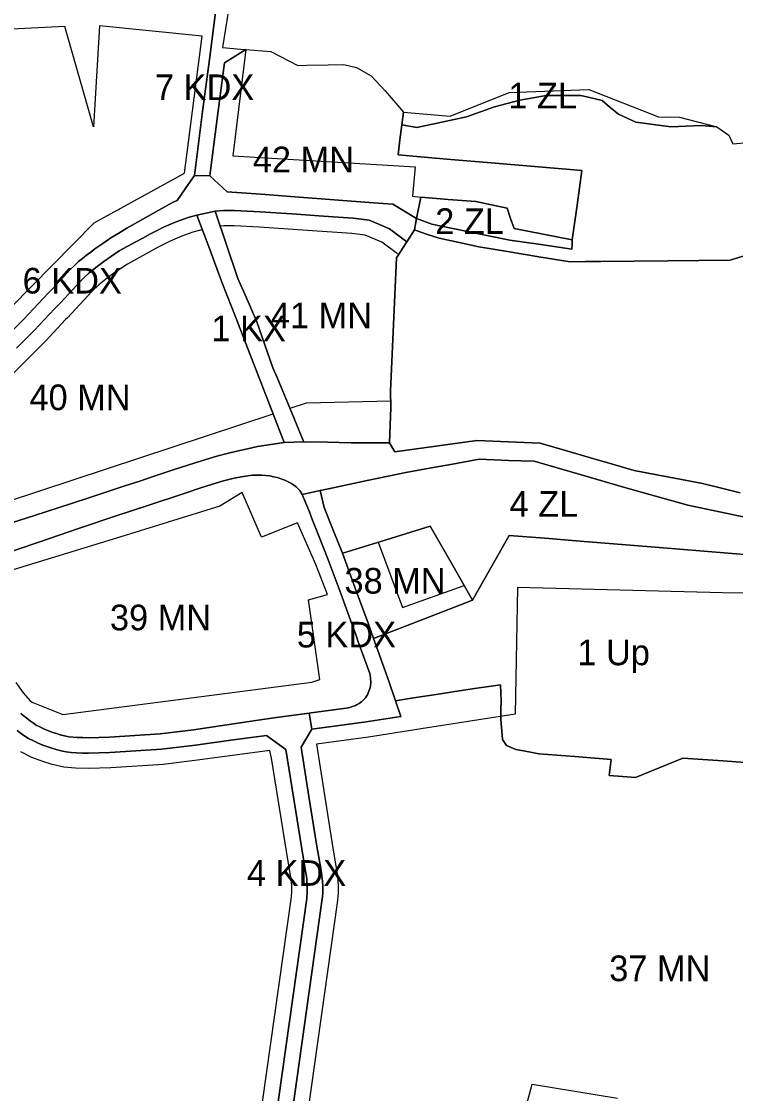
# Model space of a CAD drawing. Extents: x -294445 to -292055, y 21869 to 23693.
# Drawn here: x -293408.1 to -293130, y 23039.5 to 23457 of the extents above; entities that cross this region are included whole.
import ezdxf

# ---------------------------------------------------------------- set-up
doc = ezdxf.new("R2010")
doc.units = 0
for name, color, linetype in [('linie_rozgraniczajace', 7, 'Continuous'), ('linie_zabudowy_nieprzekraczalne', 7, 'Continuous'), ('oznaczenia_przeznaczen', 7, 'Continuous')]:
    doc.layers.add(name, color=color, linetype=linetype)

msp = doc.modelspace()

# ---------------------------------------------------------------- linework, layer by layer
at = {"layer": 'linie_rozgraniczajace'}
for points in [[(-293340.7, 23396.961), (-293339.12, 23409.431), (-293337.54, 23421.9), (-293334.86, 23442.245), (-293332.18, 23462.59), (-293331.728, 23467.542), (-293326.469, 23467.258), (-293329.78, 23446.84), (-293322.6, 23446.24), (-293320.72, 23446.05), (-293328.994, 23440.905), (-293330.292, 23431.018), (-293331.589, 23421.131), (-293333.14, 23409.034), (-293334.691, 23396.937)], [(-293334.691, 23396.937), (-293333.14, 23409.034), (-293331.589, 23421.131), (-293330.292, 23431.018), (-293328.994, 23440.905), (-293320.72, 23446.05), (-293310.92, 23445.34), (-293300.46, 23439.87), (-293296.96, 23439.94), (-293288.57, 23440.11), (-293282.51, 23440.2), (-293277.56, 23439.12), (-293271.9, 23435.79), (-293266.47, 23430.02), (-293259.28, 23421.65), (-293259.99, 23416.77), (-293260.645, 23410.89), (-293261.3, 23405.01), (-293242.445, 23403.395), (-293223.59, 23401.78), (-293206.705, 23400.37), (-293189.82, 23398.96), (-293191.685, 23385.45), (-293193.55, 23371.94), (-293204.855, 23374.15), (-293216.16, 23376.36), (-293217.55, 23380.325), (-293218.94, 23384.29), (-293225.05, 23385.57), (-293231.16, 23386.85), (-293241.858, 23387.69), (-293252.556, 23388.529), (-293254.151, 23380.288), (-293263.46, 23385.81), (-293271.009, 23386.393), (-293286.324, 23387.577), (-293301.64, 23388.76), (-293314.816, 23389.7), (-293327.993, 23390.64)], [(-293259.99, 23416.77), (-293259.28, 23421.65), (-293241.05, 23420.09), (-293218.19, 23429.39), (-293187.11, 23430.52), (-293159.95, 23419.92), (-293151.75, 23419.73), (-293137.26, 23416.03), (-293143.3, 23416.52), (-293149.205, 23416.27), (-293155.11, 23416.02), (-293161.975, 23416.895), (-293168.84, 23417.77), (-293172.165, 23419.31), (-293175.49, 23420.85), (-293178.73, 23423.535), (-293181.97, 23426.22), (-293184.668, 23426.878), (-293187.366, 23427.535), (-293190.18, 23428.24), (-293196.92, 23428.19), (-293203.66, 23428.14), (-293208.815, 23427.235), (-293213.97, 23426.33), (-293218.93, 23425.045), (-293223.89, 23423.76), (-293229.29, 23421.825), (-293234.69, 23419.89), (-293244.375, 23417.795), (-293254.06, 23415.7)], [(-293254.151, 23380.288), (-293252.556, 23388.529), (-293241.858, 23387.69), (-293231.16, 23386.85), (-293225.05, 23385.57), (-293218.94, 23384.29), (-293217.55, 23380.325), (-293216.16, 23376.36), (-293204.855, 23374.15), (-293193.55, 23371.94), (-293193.621, 23370.113), (-293193.69, 23368.36), (-293205.785, 23370.085), (-293217.88, 23371.81), (-293225.483, 23373.38), (-293233.085, 23374.95), (-293240.688, 23376.52), (-293248.29, 23378.09)], [(-293339.717, 23381.629), (-293332.604, 23383.164), (-293328.212, 23370.007), (-293323.82, 23356.85), (-293320.605, 23349.58), (-293316.38, 23340.02), (-293313.245, 23331.09), (-293310.11, 23322.16), (-293308.49, 23318.31), (-293303.405, 23306.09), (-293301.862, 23302.382), (-293298.32, 23293.87), (-293298.09, 23293.301), (-293305.786, 23293.023), (-293312.103, 23309.457), (-293318.42, 23325.89), (-293324.195, 23340.68), (-293329.97, 23355.47), (-293334.843, 23368.55)], [(-293332.604, 23383.164), (-293329.438, 23383.425), (-293327.262, 23383.429), (-293325.086, 23383.434), (-293320.108, 23383.167), (-293315.13, 23382.9), (-293302.8, 23382.05), (-293290.47, 23381.2), (-293284.68, 23380.786), (-293278.889, 23380.371), (-293272.65, 23379.682), (-293268.669, 23377.981), (-293264.687, 23376.279), (-293258.007, 23371.241), (-293262.06, 23364.96), (-293263.185, 23338.966), (-293264.311, 23312.971), (-293264.16, 23306.67), (-293264.425, 23299.77), (-293264.69, 23292.87), (-293272.195, 23292.9), (-293279.7, 23292.93), (-293288.895, 23293.115), (-293298.09, 23293.301), (-293298.32, 23293.87), (-293301.862, 23302.382), (-293303.405, 23306.09), (-293308.49, 23318.31), (-293310.11, 23322.16), (-293313.245, 23331.09), (-293316.38, 23340.02), (-293320.605, 23349.58), (-293323.82, 23356.85), (-293328.212, 23370.007)], [(-293298.776, 23272.823), (-293291.696, 23274.348), (-293290.18, 23267.78), (-293286.63, 23258.85), (-293283.08, 23249.92), (-293278.082, 23236.271), (-293273.085, 23222.623), (-293270.941, 23216.639), (-293268.124, 23208.772), (-293264.885, 23199.73), (-293262.398, 23192.398), (-293260.346, 23186.35), (-293267.068, 23185.28), (-293273.79, 23184.21), (-293284.388, 23182.776), (-293294.986, 23181.343), (-293295.962, 23187.663), (-293295.239, 23187.758), (-293280.658, 23189.726), (-293279.894, 23189.961), (-293279.184, 23190.18), (-293278.728, 23190.321), (-293277.963, 23190.625), (-293277.546, 23190.822), (-293277.083, 23191.069), (-293276.527, 23191.41), (-293276.069, 23191.73), (-293275.525, 23192.164), (-293275.095, 23192.554), (-293274.616, 23193.048), (-293274.14, 23193.614), (-293273.728, 23194.183), (-293273.335, 23194.818), (-293272.981, 23195.498), (-293272.714, 23196.119), (-293272.471, 23196.816), (-293272.275, 23197.55), (-293272.162, 23198.123), (-293272.095, 23198.601), (-293272.046, 23199.145), (-293272.029, 23199.972), (-293272.064, 23200.72), (-293272.099, 23201.469), (-293272.447, 23203.049), (-293274.729, 23209.42), (-293277.01, 23215.79), (-293277.87, 23218.19), (-293278.73, 23220.59), (-293283.708, 23234.185), (-293288.686, 23247.78), (-293292.348, 23256.991), (-293294.934, 23263.496), (-293295.924, 23265.987), (-293297.35, 23269.405)], [(-293283.08, 23249.92), (-293281.151, 23250.514), (-293265.985, 23255.185), (-293248.89, 23260.45), (-293240.64, 23246.02), (-293232.39, 23231.59), (-293234.72, 23230.69), (-293252.765, 23223.69), (-293270.941, 23216.639), (-293273.085, 23222.623), (-293278.082, 23236.271)]]:
    msp.add_lwpolyline(points, close=True, dxfattribs=at)
for points in [[(-293332.18, 23462.59), (-293334.86, 23442.245), (-293337.54, 23421.9), (-293339.12, 23409.431), (-293340.7, 23396.961), (-293344.07, 23392.156), (-293347.44, 23387.35), (-293348.925, 23386.63), (-293350.41, 23385.91), (-293358.707, 23381.184), (-293367.003, 23376.459), (-293370.111, 23374.573), (-293373.219, 23372.687), (-293376.321, 23370.558), (-293379.423, 23368.43), (-293381.066, 23367.195), (-293382.709, 23365.96), (-293384.271, 23364.717), (-293385.833, 23363.475), (-293387.501, 23361.867), (-293389.17, 23360.26), (-293392.4, 23356.77), (-293395.63, 23353.28), (-293397.61, 23351.21), (-293403.416, 23345.064), (-293407.242, 23340.987), (-293414.293, 23333.914)], [(-293261.3, 23405.01), (-293260.645, 23410.89), (-293259.99, 23416.77), (-293254.06, 23415.7), (-293244.375, 23417.795), (-293234.69, 23419.89), (-293229.29, 23421.825), (-293223.89, 23423.76), (-293218.93, 23425.045), (-293213.97, 23426.33), (-293208.815, 23427.235), (-293203.66, 23428.14), (-293196.92, 23428.19), (-293190.18, 23428.24), (-293187.366, 23427.535), (-293184.668, 23426.878), (-293181.97, 23426.22), (-293178.73, 23423.535), (-293175.49, 23420.85), (-293172.165, 23419.31), (-293168.84, 23417.77), (-293161.975, 23416.895), (-293155.11, 23416.02), (-293149.205, 23416.27), (-293143.3, 23416.52), (-293137.26, 23416.03), (-293132.61, 23412.73), (-293131.04, 23409.39), (-293122.14, 23410.09)], [(-293254.151, 23380.288), (-293248.29, 23378.09), (-293240.688, 23376.52), (-293233.085, 23374.95), (-293225.483, 23373.38), (-293217.88, 23371.81), (-293205.785, 23370.085), (-293193.69, 23368.36), (-293193.621, 23370.113), (-293193.55, 23371.94), (-293191.685, 23385.45), (-293189.82, 23398.96), (-293206.705, 23400.37), (-293223.59, 23401.78), (-293242.445, 23403.395), (-293261.3, 23405.01)], [(-293414.293, 23333.914), (-293407.242, 23340.987), (-293403.416, 23345.064), (-293397.61, 23351.21), (-293395.63, 23353.28), (-293392.4, 23356.77), (-293389.17, 23360.26), (-293387.501, 23361.867), (-293385.833, 23363.475), (-293384.271, 23364.717), (-293382.709, 23365.96), (-293381.066, 23367.195), (-293379.423, 23368.43), (-293376.321, 23370.558), (-293373.219, 23372.687), (-293370.111, 23374.573), (-293367.003, 23376.459), (-293358.707, 23381.184), (-293350.41, 23385.91), (-293348.925, 23386.63), (-293347.44, 23387.35), (-293344.07, 23392.156), (-293340.7, 23396.961), (-293334.691, 23396.937), (-293327.993, 23390.64), (-293314.816, 23389.7), (-293301.64, 23388.76), (-293286.324, 23387.577), (-293271.009, 23386.393), (-293263.46, 23385.81), (-293254.151, 23380.288), (-293255, 23375.901), (-293258.007, 23371.241), (-293264.687, 23376.279), (-293268.669, 23377.981), (-293272.65, 23379.682), (-293278.889, 23380.371), (-293284.68, 23380.786), (-293290.47, 23381.2), (-293302.8, 23382.05), (-293315.13, 23382.9), (-293320.108, 23383.167), (-293325.086, 23383.434), (-293327.262, 23383.429), (-293329.438, 23383.425), (-293332.604, 23383.164), (-293339.717, 23381.629), (-293343.114, 23380.713), (-293347.856, 23379.024), (-293352.684, 23376.849), (-293355.266, 23375.545), (-293357.848, 23374.241), (-293360.825, 23372.646), (-293363.801, 23371.051), (-293366.882, 23369.348), (-293369.963, 23367.645), (-293372.942, 23365.6), (-293375.921, 23363.556), (-293379.038, 23361.213), (-293381.875, 23358.956), (-293383.379, 23357.507), (-293384.883, 23356.058), (-293388.072, 23352.613), (-293391.26, 23349.168), (-293392.892, 23347.466), (-293394.523, 23345.764), (-293395.215, 23345.034), (-293399.072, 23340.925), (-293402.929, 23336.815), (-293410.012, 23329.71)], [(-293410.012, 23329.71), (-293402.929, 23336.815), (-293399.072, 23340.925), (-293395.215, 23345.034), (-293394.523, 23345.764), (-293392.892, 23347.466), (-293391.26, 23349.168), (-293388.072, 23352.613), (-293384.883, 23356.058), (-293383.379, 23357.507), (-293381.875, 23358.956), (-293379.038, 23361.213), (-293375.921, 23363.556), (-293372.942, 23365.6), (-293369.963, 23367.645), (-293366.882, 23369.348), (-293363.801, 23371.051), (-293360.825, 23372.646), (-293357.848, 23374.241), (-293355.266, 23375.545), (-293352.684, 23376.849), (-293347.856, 23379.024), (-293343.114, 23380.713), (-293339.717, 23381.629), (-293334.843, 23368.55), (-293329.97, 23355.47), (-293324.195, 23340.68), (-293318.42, 23325.89), (-293312.103, 23309.457), (-293305.786, 23293.023), (-293310.939, 23292.274), (-293316.092, 23291.525), (-293320.063, 23290.62), (-293324.16, 23289.684), (-293328.011, 23288.701), (-293331.987, 23287.688), (-293336.219, 23286.417), (-293340.452, 23285.147), (-293348.62, 23282.453), (-293356.787, 23279.759), (-293362, 23278.03), (-293368.18, 23275.98), (-293374.36, 23273.93), (-293381.465, 23271.57), (-293388.57, 23269.21), (-293402.96, 23264.635), (-293417.35, 23260.06)], [(-293126.594, 23365.712), (-293132, 23364), (-293144.2, 23363.89), (-293156.4, 23363.78), (-293169.4, 23363.66), (-293182.4, 23363.54), (-293188.4, 23363.48), (-293194.4, 23363.42), (-293206.6, 23365.41), (-293218.8, 23367.4), (-293224.352, 23368.32), (-293229.904, 23369.239), (-293237.652, 23370.92), (-293245.4, 23372.6), (-293249.964, 23374.054), (-293252.482, 23374.977), (-293255, 23375.901), (-293254.151, 23380.288)], [(-293264.69, 23292.87), (-293264.425, 23299.77), (-293264.16, 23306.67), (-293264.311, 23312.971), (-293263.185, 23338.966), (-293262.06, 23364.96), (-293258.007, 23371.241), (-293255, 23375.901), (-293252.482, 23374.977), (-293249.964, 23374.054), (-293245.4, 23372.6), (-293237.652, 23370.92), (-293229.904, 23369.239), (-293224.352, 23368.32), (-293218.8, 23367.4), (-293206.6, 23365.41), (-293194.4, 23363.42), (-293188.4, 23363.48), (-293182.4, 23363.54), (-293169.4, 23363.66), (-293156.4, 23363.78), (-293144.2, 23363.89), (-293132, 23364), (-293126.594, 23365.712)], [(-293417.35, 23260.06), (-293402.96, 23264.635), (-293388.57, 23269.21), (-293381.465, 23271.57), (-293374.36, 23273.93), (-293368.18, 23275.98), (-293362, 23278.03), (-293356.787, 23279.759), (-293348.62, 23282.453), (-293340.452, 23285.147), (-293336.219, 23286.417), (-293331.987, 23287.688), (-293328.011, 23288.701), (-293324.16, 23289.684), (-293320.063, 23290.62), (-293316.092, 23291.525), (-293310.939, 23292.274), (-293305.786, 23293.023), (-293298.09, 23293.301), (-293288.895, 23293.115), (-293279.7, 23292.93), (-293272.195, 23292.9), (-293264.69, 23292.87), (-293262.7, 23289.41), (-293246.71, 23291.595), (-293230.72, 23293.78), (-293218.385, 23293.285), (-293206.05, 23292.79), (-293196.23, 23289.935), (-293186.41, 23287.08), (-293177.925, 23284.575), (-293169.44, 23282.07), (-293160.59, 23280.4), (-293151.7, 23278.715), (-293142.81, 23277.03), (-293136.98, 23275.61), (-293128.19, 23273.445)], [(-293230.72, 23293.78), (-293246.71, 23291.595), (-293262.7, 23289.41), (-293264.69, 23292.87)], [(-293128.19, 23273.445), (-293136.98, 23275.61), (-293142.81, 23277.03), (-293151.7, 23278.715), (-293160.59, 23280.4), (-293169.44, 23282.07), (-293177.925, 23284.575), (-293186.41, 23287.08), (-293196.23, 23289.935), (-293206.05, 23292.79), (-293218.385, 23293.285), (-293230.72, 23293.78)], [(-293123.88, 23263.44), (-293136.22, 23266.06), (-293148.56, 23268.68), (-293160.595, 23272.015), (-293172.63, 23275.35), (-293190.51, 23280.535), (-293208.39, 23285.72), (-293213.4, 23285.9), (-293218.41, 23286.08), (-293224.08, 23286.28), (-293229.75, 23286.48), (-293240.17, 23284.61), (-293250.59, 23282.74), (-293258.32, 23281.36), (-293273.4, 23278.2), (-293288.48, 23275.04), (-293291.696, 23274.348), (-293298.776, 23272.823), (-293299.713, 23274.353), (-293301.087, 23275.739), (-293302.899, 23277.058), (-293305.464, 23278.356), (-293308.423, 23279.363), (-293309.891, 23279.692), (-293311.359, 23280.021), (-293314.414, 23280.337), (-293318.037, 23280.288), (-293321.541, 23279.852), (-293325.22, 23279.082), (-293329.314, 23278.049), (-293337.448, 23275.608), (-293345.042, 23273.103), (-293358.852, 23268.539), (-293371.208, 23264.44), (-293385.479, 23259.7), (-293401.279, 23254.271), (-293417.078, 23248.842)], [(-293123.41, 23249.1), (-293142.33, 23250.685), (-293161.25, 23252.27), (-293175.885, 23253.44), (-293190.52, 23254.61), (-293204.3, 23255.71), (-293218.08, 23256.81), (-293225.235, 23244.2), (-293232.39, 23231.59), (-293240.64, 23246.02), (-293248.89, 23260.45), (-293265.985, 23255.185), (-293281.151, 23250.514), (-293283.08, 23249.92), (-293286.63, 23258.85), (-293290.18, 23267.78), (-293291.696, 23274.348), (-293288.48, 23275.04), (-293273.4, 23278.2), (-293258.32, 23281.36), (-293250.59, 23282.74), (-293240.17, 23284.61), (-293229.75, 23286.48), (-293224.08, 23286.28), (-293218.41, 23286.08), (-293213.4, 23285.9), (-293208.39, 23285.72), (-293190.51, 23280.535), (-293172.63, 23275.35), (-293160.595, 23272.015), (-293148.56, 23268.68), (-293136.22, 23266.06), (-293123.88, 23263.44)], [(-293417.078, 23248.842), (-293401.279, 23254.271), (-293385.479, 23259.7), (-293371.208, 23264.44), (-293358.852, 23268.539), (-293345.042, 23273.103), (-293337.448, 23275.608), (-293329.314, 23278.049), (-293325.22, 23279.082), (-293321.541, 23279.852), (-293318.037, 23280.288), (-293314.414, 23280.337), (-293311.359, 23280.021), (-293309.891, 23279.692), (-293308.423, 23279.363), (-293305.464, 23278.356), (-293302.899, 23277.058), (-293301.087, 23275.739), (-293299.713, 23274.353), (-293298.776, 23272.823), (-293297.35, 23269.405), (-293295.924, 23265.987), (-293294.934, 23263.496), (-293292.348, 23256.991), (-293288.686, 23247.78), (-293283.708, 23234.185), (-293278.73, 23220.59), (-293277.87, 23218.19), (-293277.01, 23215.79), (-293274.729, 23209.42), (-293272.447, 23203.049), (-293272.099, 23201.469), (-293272.064, 23200.72), (-293272.029, 23199.972), (-293272.046, 23199.145), (-293272.095, 23198.601), (-293272.162, 23198.123), (-293272.275, 23197.55), (-293272.471, 23196.816), (-293272.714, 23196.119), (-293272.981, 23195.498), (-293273.335, 23194.818), (-293273.728, 23194.183), (-293274.14, 23193.614), (-293274.616, 23193.048), (-293275.095, 23192.554), (-293275.525, 23192.164), (-293276.069, 23191.73), (-293276.527, 23191.41), (-293277.083, 23191.069), (-293277.546, 23190.822), (-293277.963, 23190.625), (-293278.728, 23190.321), (-293279.184, 23190.18), (-293279.894, 23189.961), (-293280.658, 23189.726), (-293295.239, 23187.758), (-293295.962, 23187.663), (-293309.82, 23185.79), (-293325.449, 23183.476), (-293341.078, 23181.162), (-293347.56, 23180.389), (-293354.042, 23179.616), (-293363.903, 23178.944), (-293373.764, 23178.273), (-293377.882, 23178.151), (-293382, 23178.03), (-293384.162, 23178.075), (-293386.325, 23178.12), (-293389.643, 23178.446), (-293391.3, 23178.834), (-293392.957, 23179.222), (-293394.401, 23179.675), (-293395.845, 23180.128), (-293397.475, 23180.754), (-293399.105, 23181.379), (-293400.687, 23182.178), (-293402.27, 23182.978), (-293403.414, 23183.741), (-293404.558, 23184.503), (-293405.999, 23185.617), (-293407.439, 23186.731), (-293408.24, 23187.476)], [(-293119.25, 23167.91), (-293134.9, 23169.015), (-293150.55, 23170.12), (-293159.735, 23166.31), (-293168.92, 23162.5), (-293174.035, 23162.93), (-293179.15, 23163.36), (-293178.785, 23166.475), (-293178.42, 23169.59), (-293192.51, 23170.705), (-293206.6, 23171.82), (-293211.09, 23172.67), (-293215.58, 23173.52), (-293219.18, 23175.03), (-293220.68, 23177.38), (-293221.4, 23185.34), (-293221.35, 23188.89), (-293221.3, 23192.44), (-293221.395, 23195.565), (-293221.49, 23198.69), (-293226.1, 23197.995), (-293230.71, 23197.3), (-293237.57, 23196.27), (-293246.5, 23194.925), (-293255.43, 23193.58), (-293262.398, 23192.398), (-293264.885, 23199.73), (-293268.124, 23208.772), (-293270.941, 23216.639), (-293252.765, 23223.69), (-293234.72, 23230.69), (-293232.39, 23231.59), (-293225.235, 23244.2), (-293218.08, 23256.81), (-293204.3, 23255.71), (-293190.52, 23254.61), (-293175.885, 23253.44), (-293161.25, 23252.27), (-293142.33, 23250.685), (-293123.41, 23249.1)], [(-293308.794, 22988.328), (-293299.907, 23051.384), (-293291.02, 23114.44), (-293290.883, 23116.047), (-293290.747, 23117.654), (-293290.747, 23118.988), (-293290.748, 23120.322), (-293290.852, 23121.866), (-293290.957, 23123.411), (-293291.368, 23126.296), (-293293.011, 23135.795), (-293296.097, 23155.112), (-293299.182, 23174.43), (-293294.986, 23181.343), (-293284.388, 23182.776), (-293273.79, 23184.21), (-293267.068, 23185.28), (-293260.346, 23186.35), (-293262.398, 23192.398), (-293255.43, 23193.58), (-293246.5, 23194.925), (-293237.57, 23196.27), (-293230.71, 23197.3), (-293226.1, 23197.995), (-293221.49, 23198.69), (-293221.395, 23195.565), (-293221.3, 23192.44), (-293221.35, 23188.89), (-293221.4, 23185.34), (-293220.68, 23177.38), (-293219.18, 23175.03), (-293215.58, 23173.52), (-293211.09, 23172.67), (-293206.6, 23171.82), (-293192.51, 23170.705), (-293178.42, 23169.59), (-293178.785, 23166.475), (-293179.15, 23163.36), (-293174.035, 23162.93), (-293168.92, 23162.5), (-293159.735, 23166.31), (-293150.55, 23170.12), (-293134.9, 23169.015), (-293119.25, 23167.91)], [(-293408.24, 23187.476), (-293407.439, 23186.731), (-293405.999, 23185.617), (-293404.558, 23184.503), (-293403.414, 23183.741), (-293402.27, 23182.978), (-293400.687, 23182.178), (-293399.105, 23181.379), (-293397.475, 23180.754), (-293395.845, 23180.128), (-293394.401, 23179.675), (-293392.957, 23179.222), (-293391.3, 23178.834), (-293389.643, 23178.446), (-293386.325, 23178.12), (-293384.162, 23178.075), (-293382, 23178.03), (-293377.882, 23178.151), (-293373.764, 23178.273), (-293363.903, 23178.944), (-293354.042, 23179.616), (-293347.56, 23180.389), (-293341.078, 23181.162), (-293325.449, 23183.476), (-293309.82, 23185.79), (-293295.962, 23187.663), (-293294.986, 23181.343), (-293299.182, 23174.43), (-293296.097, 23155.112), (-293293.011, 23135.795), (-293291.368, 23126.296), (-293290.957, 23123.411), (-293290.852, 23121.866), (-293290.748, 23120.322), (-293290.747, 23118.988), (-293290.747, 23117.654), (-293290.883, 23116.047), (-293291.02, 23114.44), (-293299.907, 23051.384), (-293308.794, 22988.328)], [(-293409.694, 23180.89), (-293408.061, 23179.627), (-293406.679, 23178.706), (-293405.297, 23177.786), (-293403.418, 23176.836), (-293401.538, 23175.886), (-293399.679, 23175.173), (-293397.82, 23174.46), (-293396.181, 23173.945), (-293394.542, 23173.43), (-293392.583, 23172.972), (-293390.624, 23172.513), (-293388.652, 23172.32), (-293386.68, 23172.126), (-293384.327, 23172.077), (-293381.974, 23172.028), (-293377.781, 23172.152), (-293373.588, 23172.275), (-293363.534, 23172.958), (-293353.48, 23173.64), (-293346.9, 23174.425), (-293340.32, 23175.21), (-293326.505, 23177.079), (-293312.69, 23178.948), (-293305.102, 23173.453), (-293302.016, 23154.132), (-293298.93, 23134.81), (-293297.295, 23125.361), (-293297.112, 23124.073), (-293296.927, 23122.781), (-293296.748, 23120.119), (-293296.743, 23117.984), (-293296.941, 23115.409), (-293314.72, 22989.27)], [(-293314.72, 22989.27), (-293296.941, 23115.409), (-293296.743, 23117.984), (-293296.748, 23120.119), (-293296.927, 23122.781), (-293297.112, 23124.073), (-293297.295, 23125.361), (-293298.93, 23134.81), (-293302.016, 23154.132), (-293305.102, 23173.453), (-293312.69, 23178.948), (-293326.505, 23177.079), (-293340.32, 23175.21), (-293346.9, 23174.425), (-293353.48, 23173.64), (-293363.534, 23172.958), (-293373.588, 23172.275), (-293377.781, 23172.152), (-293381.974, 23172.028), (-293384.327, 23172.077), (-293386.68, 23172.126), (-293388.652, 23172.32), (-293390.624, 23172.513), (-293392.583, 23172.972), (-293394.542, 23173.43), (-293396.181, 23173.945), (-293397.82, 23174.46), (-293399.679, 23175.173), (-293401.538, 23175.886), (-293403.418, 23176.836), (-293405.297, 23177.786), (-293406.679, 23178.706), (-293408.061, 23179.627), (-293409.694, 23180.89)]]:
    msp.add_lwpolyline(points, dxfattribs=at)
at = {"layer": 'linie_zabudowy_nieprzekraczalne'}
for points in [[(-293377.626, 23455.293), (-293380.028, 23415.915), (-293391.219, 23455.055), (-293544.049, 23447.456), (-293548.238, 23447.056), (-293541.27, 23377.389), (-293532.626, 23294.288), (-293524.349, 23241.364), (-293458.796, 23250.626), (-293459.789, 23258.564), (-293469.06, 23276.757), (-293474.026, 23274.772), (-293492.565, 23319.186), (-293453.167, 23328.779), (-293450.519, 23320.179), (-293428.668, 23329.11), (-293420.391, 23337.379), (-293379.776, 23378.546), (-293344.606, 23397.955), (-293337.705, 23451.274), (-293377.626, 23455.293)], [(-293320.72, 23446.05), (-293325.796, 23404.671), (-293254.73, 23400.36), (-293255.816, 23388.954), (-293252.556, 23388.529)], [(-293337.6, 23375.948), (-293338.302, 23375.796), (-293341.324, 23374.981), (-293345.613, 23373.453), (-293350.099, 23371.433), (-293355.078, 23368.918), (-293360.932, 23365.781), (-293366.806, 23362.534), (-293372.42, 23358.682), (-293375.367, 23356.466), (-293377.917, 23354.438), (-293380.597, 23351.857), (-293386.892, 23345.054), (-293390.18, 23341.625), (-293390.85, 23340.917), (-293398.616, 23332.643), (-293413.001, 23318.213)], [(-293261.62, 23366.451), (-293267.717, 23371.049), (-293274.191, 23373.816), (-293279.433, 23374.395), (-293290.89, 23375.215), (-293315.497, 23376.911), (-293325.24, 23377.433), (-293329.185, 23377.426), (-293330.648, 23377.305)], [(-293303.365, 23306.341), (-293297.111, 23308.42), (-293264.223, 23309.288)], [(-293439.936, 23261.41), (-293310.097, 23304.238)], [(-293300.598, 23261.741), (-293314.595, 23256.148), (-293322.085, 23273.608), (-293322.085, 23273.608), (-293322.085, 23273.608), (-293330.739, 23268.195), (-293330.739, 23268.195), (-293330.739, 23268.195), (-293330.739, 23268.195), (-293330.739, 23268.195), (-293371.087, 23255.748), (-293415.548, 23242.094)], [(-293410.233, 23199.517), (-293407.416, 23195.54), (-293404.707, 23192.384), (-293404.707, 23192.384), (-293403.585, 23191.756), (-293391.98, 23187.084), (-293391.98, 23187.084), (-293391.98, 23187.084), (-293391.98, 23187.084), (-293391.98, 23187.084), (-293391.98, 23187.084), (-293391.98, 23187.084), (-293391.98, 23187.084), (-293391.98, 23187.084), (-293294.96, 23199.696), (-293294.96, 23199.696), (-293294.96, 23199.696), (-293291.8, 23200.693), (-293296.211, 23231.729), (-293288.859, 23233.799), (-293293.454, 23245.552), (-293300.604, 23261.739)], [(-293269.17, 23254.204), (-293259.627, 23228.778), (-293235.702, 23237.383)], [(-293019.96, 23201.461), (-293063.951, 23214.173), (-293115.246, 23221.128), (-293114.513, 23234.306), (-293135.08, 23234.48), (-293214.903, 23236.502), (-293215.814, 23187.234), (-293252.379, 23181.543), (-293272.916, 23178.274), (-293293.216, 23175.527), (-293287.092, 23136.779), (-293285.441, 23127.231), (-293284.985, 23124.037), (-293284.748, 23120.526), (-293284.747, 23117.401), (-293285.056, 23113.767), (-293302.86, 22987.439)], [(-293320.654, 22990.16), (-293302.908, 23116.063), (-293302.747, 23118.122), (-293302.748, 23119.915), (-293302.899, 23122.157), (-293303.223, 23124.426), (-293304.849, 23133.825), (-293310.635, 23170.052), (-293311.313, 23173.079), (-293339.562, 23169.258), (-293352.921, 23167.664), (-293373.296, 23166.281), (-293381.948, 23166.027), (-293387.036, 23166.132), (-293391.605, 23166.581), (-293396.127, 23167.639), (-293399.795, 23168.791), (-293403.972, 23170.393), (-293408.325, 23172.593)], [(-293228.475, 22970.823), (-293209.126, 23043.154), (-293175.962, 23037.665)]]:
    msp.add_lwpolyline(points, dxfattribs=at)

# ---------------------------------------------------------------- texts
at = {"layer": 'oznaczenia_przeznaczen'}
for s, p in [('7 KDX', (-293356.055, 23426.405)), ('1 ZL', (-293218.474, 23423.14)), ('42 MN', (-293317.95, 23398.266)), ('2 ZL', (-293246.925, 23374.236)), ('6 KDX', (-293407.609, 23351.058)), ('41 MN', (-293310.931, 23337.524)), ('1 KX', (-293334.095, 23332.478)), ('40 MN', (-293404.946, 23305.618)), ('4 ZL', (-293217.97, 23264.095)), ('38 MN', (-293282.263, 23234.178)), ('39 MN', (-293373.588, 23219.874)), ('5 KDX', (-293300.82, 23213.19)), ('1 Up', (-293191.565, 23206.29)), ('4 KDX', (-293320.245, 23120.361)), ('37 MN', (-293179.151, 23083.233))]:
    msp.add_text(s, height=10, dxfattribs=at).set_placement(p)

doc.saveas('drawing.dxf')
